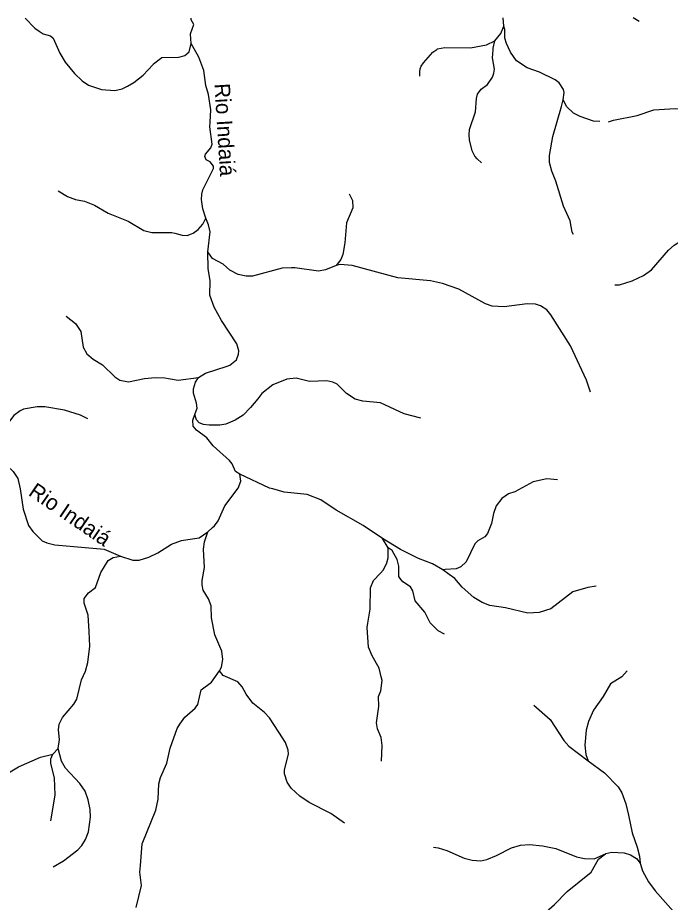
# Model space of a CAD drawing. Extents: x 473.9 to 500, y 7733.1 to 7760.8.
# Drawn here: x 477.26 to 481.48, y 7755.08 to 7760.81 of the extents above; entities that cross this region are included whole.
import ezdxf
from ezdxf.enums import TextEntityAlignment as Align

# ---------------------------------------------------------------- set-up
doc = ezdxf.new("R2010")
doc.units = 0
doc.header["$LTSCALE"] = 0.032
doc.layers.add('61', color=7, linetype='Continuous')
doc.layers.add('7', color=7, linetype='Continuous', lineweight=25)

msp = doc.modelspace()

# ---------------------------------------------------------------- linework, layer by layer
at = {"layer": '7'}
for p, q in [((480.4048, 7760.7549), (480.4014, 7760.8102)), ((481.2809, 7760.7853), (481.243, 7760.8108)), ((479.6568, 7757.3756), (479.6189, 7757.436)), ((477.4835, 7756.0385), (477.5194, 7756.0755))]:
    msp.add_line(p, q, dxfattribs=at)
for points in [[(477.306, 7760.8079), (477.3679, 7760.7425), (477.3962, 7760.7239), (477.4221, 7760.7069), (477.4691, 7760.6924), (477.4858, 7760.6791), (477.5294, 7760.5805), (477.5649, 7760.5236), (477.6256, 7760.4492), (477.6739, 7760.4022), (477.715, 7760.3745), (477.7991, 7760.3454), (477.8857, 7760.3383), (477.9337, 7760.3496), (477.9679, 7760.3682), (478.0093, 7760.3908), (478.0687, 7760.4382), (478.134, 7760.5081), (478.1373, 7760.5117), (478.1896, 7760.553), (478.2975, 7760.5561), (478.309, 7760.5564), (478.3391, 7760.5659), (478.3676, 7760.5898), (478.381, 7760.6437)], [(478.381, 7760.6437), (478.3761, 7760.7044), (478.376, 7760.7058), (478.3967, 7760.7671), (478.3809, 7760.7964), (478.3809, 7760.8087)], [(480.3471, 7760.6615), (480.3853, 7760.7093), (480.4048, 7760.7549)], [(480.7904, 7760.2796), (480.7958, 7760.3251), (480.7925, 7760.3452), (480.7628, 7760.3887), (480.7377, 7760.409), (480.6355, 7760.4572), (480.5569, 7760.4861), (480.4877, 7760.5308), (480.4479, 7760.5865), (480.4223, 7760.6426), (480.4123, 7760.6778), (480.4108, 7760.7333), (480.4048, 7760.7549)], [(478.4754, 7759.5127), (478.4558, 7759.5733), (478.4465, 7759.6337), (478.4497, 7759.6676), (478.4567, 7759.6962), (478.5258, 7759.8344), (478.5251, 7759.8497), (478.5031, 7759.8761), (478.4781, 7759.8907), (478.4691, 7759.9114), (478.4738, 7759.9269), (478.5084, 7759.9673), (478.5154, 7759.9919), (478.5011, 7760.103), (478.5031, 7760.1329), (478.5084, 7760.2145), (478.4932, 7760.3126), (478.4755, 7760.3716), (478.4614, 7760.4692), (478.4299, 7760.5544), (478.381, 7760.6437)], [(479.8615, 7760.4309), (479.8611, 7760.4605), (479.8642, 7760.4786), (479.8705, 7760.4963), (479.8853, 7760.5186), (479.9461, 7760.5879), (479.9705, 7760.6052), (479.976, 7760.6091), (480.0239, 7760.6173), (480.1894, 7760.6153), (480.2926, 7760.6351), (480.3471, 7760.6615)], [(480.2603, 7759.871), (480.2325, 7759.8954), (480.2174, 7759.9143), (480.2009, 7759.9486), (480.1832, 7760.0184), (480.1799, 7760.052), (480.1833, 7760.0873), (480.2219, 7760.1999), (480.2271, 7760.2874), (480.2346, 7760.3158), (480.2578, 7760.347), (480.2983, 7760.3781), (480.3308, 7760.4244), (480.34, 7760.4506), (480.345, 7760.4779), (480.3327, 7760.5517), (480.3351, 7760.6032), (480.3356, 7760.6144), (480.3471, 7760.6615)], [(480.8558, 7759.4058), (480.8481, 7759.4214), (480.8351, 7759.4954), (480.7905, 7759.5889), (480.7415, 7759.7523), (480.715, 7759.8164), (480.7012, 7759.8732), (480.7012, 7759.9185), (480.722, 7760.042), (480.7776, 7760.2352), (480.7904, 7760.2796)], [(481.0275, 7760.1374), (480.9852, 7760.141), (480.8997, 7760.1704), (480.857, 7760.1914), (480.8135, 7760.2342), (480.7904, 7760.2796)], [(481.0832, 7760.1361), (481.1147, 7760.1475), (481.2679, 7760.1781), (481.3772, 7760.213), (481.5149, 7760.2221), (481.7071, 7760.2132), (481.7717, 7760.228), (481.8606, 7760.262), (481.8772, 7760.2632)], [(477.5183, 7759.6889), (477.5798, 7759.6532), (477.6308, 7759.6333), (477.6903, 7759.6212), (477.7535, 7759.596), (477.8424, 7759.5434), (477.9712, 7759.4927), (478.0733, 7759.432), (478.1251, 7759.418), (478.2549, 7759.4186), (478.2753, 7759.4136), (478.3223, 7759.4019), (478.3544, 7759.4002), (478.3828, 7759.4108), (478.3924, 7759.4144), (478.4252, 7759.4381), (478.4551, 7759.4724), (478.4754, 7759.5127)], [(479.4043, 7759.6697), (479.4254, 7759.6257), (479.4279, 7759.5781), (479.3864, 7759.4822), (479.3751, 7759.3525), (479.3621, 7759.2768), (479.3487, 7759.2433), (479.3201, 7759.2048)], [(478.4885, 7759.2942), (478.5027, 7759.4239), (478.4934, 7759.468), (478.4754, 7759.5127)], [(481.1236, 7759.079), (481.1546, 7759.0805), (481.2361, 7759.105), (481.3094, 7759.1402), (481.3612, 7759.1766), (481.4711, 7759.3049), (481.5079, 7759.3362), (481.5325, 7759.3527), (481.6077, 7759.3804), (481.6622, 7759.411)], [(478.4281, 7758.4788), (478.4728, 7758.5084), (478.6139, 7758.5537), (478.6312, 7758.5593), (478.6748, 7758.5942), (478.6877, 7758.6314), (478.6886, 7758.6513), (478.6767, 7758.6976), (478.5766, 7758.8483), (478.5282, 7758.9346), (478.5011, 7759.0134), (478.5026, 7759.1058), (478.4915, 7759.1735), (478.4899, 7759.1834), (478.4885, 7759.2942)], [(479.3201, 7759.2048), (479.2509, 7759.1778), (479.2044, 7759.1693), (479.0516, 7759.1893), (479.0307, 7759.1891), (478.9706, 7759.1885), (478.7774, 7759.1356), (478.7361, 7759.1356), (478.6843, 7759.1467), (478.6316, 7759.1754), (478.5882, 7759.2143), (478.5182, 7759.2499), (478.4885, 7759.2942)], [(480.9663, 7758.3847), (480.9409, 7758.4627), (480.8376, 7758.6847), (480.7096, 7758.8849), (480.6825, 7758.9169), (480.6428, 7758.9442), (480.6101, 7758.9543), (480.5562, 7758.9568), (480.4068, 7758.9368), (480.3291, 7758.9415), (480.2861, 7758.9566), (480.1145, 7759.0513), (480.0073, 7759.0886), (479.9298, 7759.1059), (479.7194, 7759.1252), (479.4236, 7759.2056), (479.3458, 7759.2109), (479.3201, 7759.2048)], [(477.57, 7758.8776), (477.6313, 7758.8283), (477.6664, 7758.7779), (477.6802, 7758.6756), (477.7041, 7758.6332), (477.7446, 7758.5991), (477.8065, 7758.5617), (477.8863, 7758.4843), (477.9187, 7758.4622), (477.9744, 7758.4509), (478.079, 7758.4725), (478.1463, 7758.4797), (478.2089, 7758.4774), (478.2338, 7758.473), (478.2964, 7758.4621), (478.4281, 7758.4788)], [(478.4031, 7758.2389), (478.4193, 7758.2803), (478.4153, 7758.3142), (478.3953, 7758.3784), (478.3953, 7758.4052), (478.4081, 7758.4492), (478.4281, 7758.4788)], [(479.8679, 7758.2156), (479.7596, 7758.2442), (479.6059, 7758.3153), (479.4913, 7758.3258), (479.4414, 7758.3392), (479.3868, 7758.375), (479.3263, 7758.4362), (479.2984, 7758.4496), (479.2582, 7758.4573), (479.1461, 7758.4532), (479.061, 7758.475), (478.9997, 7758.4677), (478.9093, 7758.432), (478.8384, 7758.3753), (478.8109, 7758.3416), (478.7645, 7758.2847), (478.7162, 7758.2353), (478.6656, 7758.2028), (478.6039, 7758.1781), (478.5648, 7758.1696), (478.4975, 7758.1696), (478.4602, 7758.176), (478.432, 7758.1866), (478.4137, 7758.2055), (478.4031, 7758.2389)], [(477.7102, 7758.2126), (477.6638, 7758.2344), (477.5594, 7758.2673), (477.4317, 7758.2905), (477.383, 7758.2905), (477.2949, 7758.2743), (477.2728, 7758.264), (477.2325, 7758.2342), (477.1911, 7758.1801)], [(478.6954, 7757.8537), (478.6679, 7757.8705), (478.6457, 7757.9194), (478.6275, 7757.942), (478.523, 7758.0361), (478.4818, 7758.0876), (478.4147, 7758.1387), (478.3939, 7758.1635), (478.392, 7758.2036), (478.4031, 7758.2389)], [(477.2076, 7757.8896), (477.2271, 7757.8711), (477.2567, 7757.8251), (477.2734, 7757.7588), (477.292, 7757.6263), (477.3268, 7757.5202), (477.3543, 7757.481), (477.4148, 7757.4218), (477.4448, 7757.4073), (477.4983, 7757.3954), (477.816, 7757.3677), (477.9231, 7757.3226)], [(478.4876, 7757.4802), (478.5186, 7757.5081), (478.5304, 7757.5188), (478.5555, 7757.5504), (478.5982, 7757.6477), (478.6856, 7757.7632), (478.7023, 7757.8087), (478.6954, 7757.8537)], [(479.6189, 7757.436), (479.4933, 7757.521), (479.3203, 7757.6206), (479.2204, 7757.6871), (479.1309, 7757.7221), (478.983, 7757.7373), (478.9092, 7757.7574), (478.8867, 7757.7635), (478.6954, 7757.8537)], [(480.7516, 7757.8162), (480.6836, 7757.8222), (480.5956, 7757.8039), (480.4753, 7757.7394), (480.435, 7757.7252), (480.3918, 7757.6957), (480.3561, 7757.6476), (480.3389, 7757.598), (480.3258, 7757.5335), (480.2991, 7757.4695), (480.2816, 7757.4477), (480.2359, 7757.4211), (480.2176, 7757.4013), (480.1622, 7757.2857), (480.1266, 7757.2528), (480.0969, 7757.2391), (480.0244, 7757.235), (480.0103, 7757.233)], [(477.9231, 7757.3226), (478.0016, 7757.2965), (478.0437, 7757.296), (478.1061, 7757.3152), (478.1633, 7757.343), (478.2524, 7757.4004), (478.3186, 7757.423), (478.3576, 7757.4294), (478.431, 7757.4414), (478.4876, 7757.4802)], [(478.5642, 7756.5797), (478.5764, 7756.6023), (478.5845, 7756.6527), (478.5781, 7756.7058), (478.5332, 7756.8117), (478.5123, 7756.9223), (478.5091, 7757.0009), (478.4926, 7757.0455), (478.4587, 7757.1019), (478.4514, 7757.1352), (478.4514, 7757.1637), (478.4673, 7757.2479), (478.4594, 7757.3675), (478.4658, 7757.4152), (478.4876, 7757.4802)], [(480.0103, 7757.233), (479.9431, 7757.2712), (479.8531, 7757.3074), (479.7364, 7757.3641), (479.6189, 7757.436)], [(479.612, 7755.9928), (479.618, 7756.095), (479.61, 7756.1459), (479.5868, 7756.2023), (479.5794, 7756.2425), (479.5962, 7756.3483), (479.5931, 7756.4124), (479.6077, 7756.4503), (479.6171, 7756.5169), (479.6114, 7756.54), (479.5977, 7756.5958), (479.552, 7756.676), (479.5291, 7756.7328), (479.521, 7756.8596), (479.5254, 7756.887), (479.5403, 7756.979), (479.5419, 7757.1176), (479.5611, 7757.1632), (479.6038, 7757.2092), (479.6255, 7757.2327), (479.6471, 7757.2777), (479.6564, 7757.3104), (479.6568, 7757.3756)], [(480.02, 7756.8167), (479.9792, 7756.8381), (479.927, 7756.8901), (479.8943, 7756.9594), (479.8313, 7757.0317), (479.8147, 7757.0979), (479.8012, 7757.1241), (479.7516, 7757.1563), (479.7336, 7757.1766), (479.7258, 7757.1906), (479.7245, 7757.2566), (479.7152, 7757.3005), (479.6813, 7757.3594), (479.6568, 7757.3756)], [(477.5194, 7756.0755), (477.5276, 7756.135), (477.5213, 7756.1967), (477.5248, 7756.2326), (477.5479, 7756.2767), (477.6196, 7756.362), (477.6399, 7756.3951), (477.67, 7756.5196), (477.6964, 7756.5758), (477.7113, 7756.6321), (477.7233, 7756.7379), (477.7201, 7756.8347), (477.7121, 7756.9387), (477.6865, 7757.0169), (477.6871, 7757.0472), (477.7143, 7757.0836), (477.7606, 7757.1181), (477.7951, 7757.2171), (477.8436, 7757.2938), (477.875, 7757.3137), (477.9231, 7757.3226)], [(481.0023, 7757.1284), (480.9497, 7757.1191), (480.8516, 7757.0901), (480.7095, 7756.9815), (480.6338, 7756.9564), (480.5598, 7756.9516), (480.4163, 7756.9867), (480.3139, 7757.0026), (480.2652, 7757.0218), (480.211, 7757.0541), (480.1347, 7757.1219), (480.0871, 7757.1782), (480.0514, 7757.2037), (480.0103, 7757.233)], [(478.025, 7755.0459), (478.0584, 7755.1873), (478.0481, 7755.2753), (478.0516, 7755.3173), (478.0633, 7755.457), (478.1515, 7755.6754), (478.1675, 7755.7473), (478.1698, 7755.8469), (478.1817, 7755.8887), (478.2229, 7755.9816), (478.2438, 7756.0779), (478.2905, 7756.2049), (478.3061, 7756.2336), (478.3391, 7756.278), (478.4058, 7756.3374), (478.4234, 7756.3617), (478.4445, 7756.4557), (478.511, 7756.5046), (478.5642, 7756.5797)], [(479.3728, 7755.5914), (479.2846, 7755.6553), (479.1437, 7755.7267), (479.0829, 7755.7659), (479.0276, 7755.8189), (479.0019, 7755.8583), (478.9845, 7755.9112), (478.9838, 7755.9368), (479.0101, 7756.0384), (479.0092, 7756.0638), (478.9913, 7756.1151), (478.9486, 7756.1806), (478.8881, 7756.2735), (478.8557, 7756.3083), (478.7795, 7756.3692), (478.7361, 7756.4278), (478.7107, 7756.4746), (478.6825, 7756.5071), (478.5867, 7756.5479), (478.5642, 7756.5797)], [(481.2041, 7756.5799), (481.1695, 7756.5408), (481.0954, 7756.4957), (481.0487, 7756.4117), (480.9867, 7756.3232), (480.9543, 7756.2501), (480.9392, 7756.1943), (480.9304, 7756.0973), (480.9369, 7756.0373), (480.9509, 7755.996)], [(480.5986, 7756.3574), (480.7042, 7756.2644), (480.7927, 7756.1271), (480.826, 7756.0914), (480.9509, 7755.996)], [(477.0082, 7755.475), (477.0127, 7755.5842), (477.0432, 7755.6744), (477.08, 7755.753), (477.1666, 7755.8889), (477.2079, 7755.9251), (477.2624, 7755.9565), (477.4049, 7756.0201), (477.4835, 7756.0385)], [(477.4712, 7755.6063), (477.4988, 7755.7729), (477.4956, 7755.8855), (477.4724, 7755.9794), (477.4716, 7756.0089), (477.4835, 7756.0385)], [(477.4873, 7755.3087), (477.5543, 7755.3478), (477.6452, 7755.4182), (477.6712, 7755.4462), (477.6956, 7755.4865), (477.7151, 7755.5349), (477.7289, 7755.6312), (477.7265, 7755.6802), (477.7138, 7755.7437), (477.6931, 7755.7995), (477.6589, 7755.8493), (477.5662, 7755.948), (477.541, 7755.9926), (477.5194, 7756.0755)], [(480.9509, 7755.996), (481.0579, 7755.9182), (481.1466, 7755.8264), (481.1692, 7755.7876), (481.195, 7755.7168), (481.2114, 7755.6431), (481.2367, 7755.5294), (481.2682, 7755.4356), (481.2831, 7755.3787), (481.287, 7755.3326), (481.2873, 7755.3318)], [(479.9491, 7755.4354), (479.9808, 7755.4329), (480.0354, 7755.4153), (480.1474, 7755.3645), (480.1995, 7755.3511), (480.2572, 7755.348), (480.2956, 7755.356), (480.3579, 7755.3817), (480.4548, 7755.4328), (480.5129, 7755.4492), (480.5703, 7755.4546), (480.6559, 7755.4458), (480.7425, 7755.4282), (480.8765, 7755.3748), (480.9267, 7755.3639), (480.991, 7755.3609), (481.0626, 7755.3936)], [(480.3268, 7754.5144), (480.3955, 7754.6558), (480.4854, 7754.773), (480.5862, 7754.9244), (480.6452, 7754.9881), (480.733, 7755.064), (480.815, 7755.1485), (480.9701, 7755.2753), (481.0187, 7755.3592), (481.0626, 7755.3936)], [(481.0626, 7755.3936), (481.0661, 7755.3964), (481.1049, 7755.404), (481.1835, 7755.3989), (481.2252, 7755.3873), (481.2638, 7755.3626), (481.2873, 7755.3318)], [(481.2873, 7755.3318), (481.3035, 7755.284), (481.3429, 7755.2123), (481.3853, 7755.1545), (481.6194, 7754.8875), (481.6812, 7754.7882), (481.7064, 7754.7588), (481.7416, 7754.726), (481.8047, 7754.6895), (481.8339, 7754.6566)]]:
    msp.add_lwpolyline(points, dxfattribs=at)

# ---------------------------------------------------------------- texts
at = {"layer": '61'}
for rotation, p in [(273.469, (478.5491, 7760.082)), (325.623, (477.5686, 7757.5509))]:
    msp.add_text('Rio Indaiá', height=0.1, rotation=rotation, dxfattribs=at).set_placement(p, align=Align.CENTER)

doc.saveas('drawing.dxf')
